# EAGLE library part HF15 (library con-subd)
SUB-D
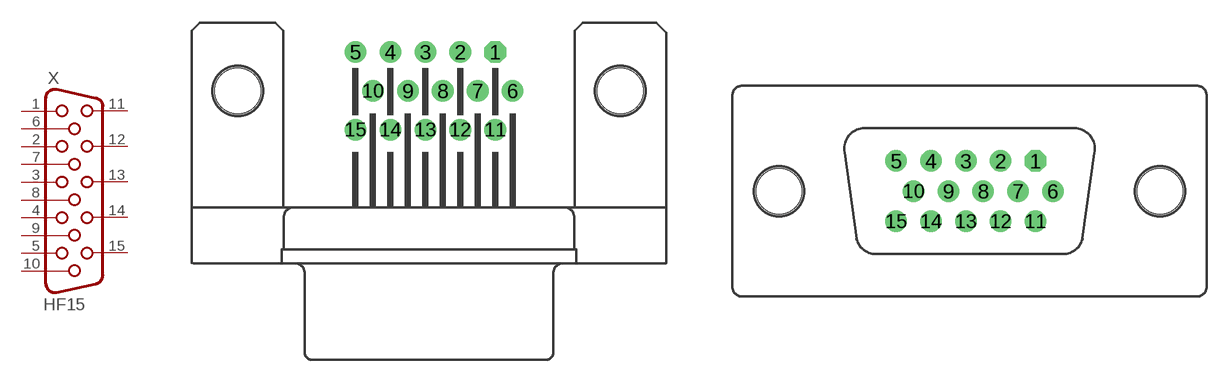
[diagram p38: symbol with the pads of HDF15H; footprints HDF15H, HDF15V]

Designator prefix X

## HF15H (OC_FARNELL: unknown; OC_NEWARK: unknown)  [HDF15H]
1  1  pas
2  2  pas
3  3  pas
4  4  pas
5  5  pas
6  6  pas
7  7  pas
8  8  pas
9  9  pas
10  10  pas
11  11  pas
12  12  pas
13  13  pas
14  14  pas
15  15  pas

## HF15V (OC_FARNELL: unknown; OC_NEWARK: unknown)  [HDF15V]
Pads as for HDF15H

## Footprint HDF15H (pad centres in mm)
SUB-D
drill 0.9 octagon: 1 4.329,2.54
drill 0.9 round: 2 2.043,2.54; 3 -0.243,2.54; 4 -2.529,2.54; 5 -4.815,2.54; 6 5.472,0; 7 3.186,0; 8 0.9,0; 9 -1.386,0; 10 -3.672,0; 11 4.329,-2.54; 12 2.043,-2.54; 13 -0.243,-2.54; 14 -2.529,-2.54; 15 -4.815,-2.54
hole 3 at -12.5,0
hole 3 at 12.5,0

## Footprint HDF15V (pad centres in mm)
SUB-D
drill 0.9 octagon: 1 4.329,1.98
drill 0.9 round: 2 2.043,1.98; 3 -0.243,1.98; 4 -2.529,1.98; 5 -4.815,1.98; 6 5.472,0; 7 3.186,0; 8 0.9,0; 9 -1.386,0; 10 -3.672,0; 11 4.329,-1.98; 12 2.043,-1.98; 13 -0.243,-1.98; 14 -2.529,-1.98; 15 -4.815,-1.98
hole 3 at -12.5,0
hole 3 at 12.5,0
